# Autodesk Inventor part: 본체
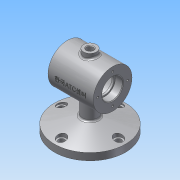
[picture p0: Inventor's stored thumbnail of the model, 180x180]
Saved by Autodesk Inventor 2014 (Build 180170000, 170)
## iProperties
Created: 2018-12
Part Number: 본체
Material: 알루미늄 6061
Document SubType Name: Modeling
Designer: sda
Mass: 688.56 g
Surface Area: 557.83 cm^2
Volume: 254.081 cm^3
Density: 2.71 g/cm^3
Appearance: 알루미늄 - 평지
Author: sda
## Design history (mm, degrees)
sketch "스케치1"
  geometry: C1 r 55 at (0, 0); 1 further point
  constraints: 1 centre point, 1 coincident
  dimensions: "d0" = 110 diameter of C1
extrude "돌출1" new body sketch "스케치1" distance "d1" = 11; taper "d2" = 0 deg
node "작업 평면1"
sketch "스케치2"
  geometry: L1 (55, 11)-(-55, 11) reference; L2 (55, 11)-(0, 25.737); L3 (0, 25.737)-(0, 11); L4 (55, 0)-(55, 11) reference; 1 further point
  constraints: 4 end point, 1 midpoint, 1 vertical
  dimensions: "d5" = 75 deg angle of L4 L2
revolve "회전1" sketch "스케치2" stored, may be unused: angle "d6" = 90 deg
node "작업 평면2"
node "작업 평면3"
node "작업 평면5"
sketch "스케치6"
  geometry: L1 (0, 0)-(35, 0); L2 (0, 0)-(-35, 0); L3 (-35, 0)-(-35, -30); L4 (-35, -30)-(35, -30); L5 (35, -30)-(35, 0); C1 r 55 at (0, 0) reference; 2 further points
  constraints: 10 end point, 2 perpendicular, 1 collinear, 1 horizontal, 1 parallel
  dimensions: "d38" = 35 distance of L1.start L1.end; "d39" = 35 distance of L1.start L2.end; "d40" = 30 distance of L2.end L3.end
revolve "회전4" sketch "스케치6" stored, may be unused: angle "d41" = 90 deg
sketch "스케치7"
  geometry: L1 (0, 25.737)-(55, 11) reference; L2 (55, 11)-(55, 0) reference; L3 (55, 0)-(-55, 0) reference; L4 (-55, 0)-(-55, 11) reference; L5 (-55, 11)-(0, 25.737) reference; L6 (-35, 45)-(-35, 105) reference; L7 (-35, 105)-(35, 105) reference; L8 (35, 105)-(35, 45) reference; L9 (35, 45)-(-35, 45) reference; L10 (55, 11)-(55, 0) reference; L11 (55, 0)-(-55, 0) reference; L12 (-55, 0)-(-55, 11) reference; L13 (-35, 45)-(-35, 105) reference; L14 (-35, 105)-(35, 105) reference; L15 (35, 105)-(35, 45) reference; L16 (35, 45)-(-35, 45) reference; L17 (-35, 75)-(35, 75); L18 (-35, 91)-(-23, 91); L19 (-23, 91)-(-23, 89); L20 (-23, 89)-(-20, 89); L21 (-20, 89)-(-20, 100); L22 (-20, 100)-(20, 100); L23 (20, 100)-(20, 89); L24 (20, 89)-(23, 89); L25 (23, 89)-(23, 91); L26 (23, 91)-(35, 91); L27 (0, 25.737)-(55, 11) reference; L28 (-55, 11)-(0, 25.737) reference; 1 further point
  constraints: 20 end point, 7 parallel, 2 midpoint, 2 perpendicular, 2 point on line
  dimensions: "d42" = 50 diameter of L22 L17; "d44" = 28 diameter of L20 L17; "d45" = 28 diameter of L24 L17; "d46" = 32 diameter of L26 L17; "d47" = 32 diameter of L18 L17; "d48" = 3 distance between parallel lines of L21 L19; "d49" = 3 distance between parallel lines of L25 L23; "d50" = 40 distance between parallel lines of L23 L21; "d51" = 12 distance between parallel lines of L19 L6
revolve "회전5" sketch "스케치7" stored, may be unused: angle "d52" = 90 deg
chamfer "모따기3" distance "d53" = 1; stored, may be unused: second distance "d54" = 2, angle "d55" = 45 deg
chamfer "모따기4" distance "d56" = 1; stored, may be unused: second distance "d57" = 2, angle "d58" = 45 deg
fillet "모깎기3" dims "d59" = 0.3
fillet "모깎기4" dims "d60" = 3
sketch "스케치8"
  geometry: L1 (35, 45)-(35, 105) reference; L2 (-35, 45)-(-35, 105) reference; L3 (-35, 45)-(35, 45) reference; L4 (0, 25.737)-(55, 11) reference; L5 (0, 45)-(0, 25.737); L6 (12, 45)-(12, 22.522); 1 further point
  constraints: 4 end point, 2 point on line, 1 midpoint, 1 parallel, 1 perpendicular
  dimensions: "d61" = 12 distance between parallel lines of L6 L5
revolve "회전6" sketch "스케치8" stored, may be unused: angle "d62" = 90 deg
sketch "스케치9"
  geometry: A1 r 12 centre (0, 0) between (12, 0) and (-12, 0) reference; 1 further point
  constraints: 1 coincident, 1 horizontal alignment, 2 other
extrude "돌출2" join sketch "스케치9" stored distance "d63" = 10; taper "d64" = 0 deg
node "작업 평면6"
sketch "스케치10"
  geometry: C1 r 10 at (0, 0); 1 further point
  constraints: 1 centre point, 1 coincident
  dimensions: "d66" = 20 diameter of C1
extrude "돌출3" join sketch "스케치10" stored distance "d67" = 10; taper "d68" = 0 deg
hole "구멍1" diameter "d71" = 10; stored, may be unused: countersink angle "d75" = 90 deg, drill point angle "d77" = 118 deg; dims "d69" = 10, "d70" = 10, "d72" = 6, "d73" = 4, "d74" = 2, "d76" = 8
chamfer "모따기5" distance "d78" = 1; stored, may be unused: second distance "d79" = 2, angle "d80" = 45 deg
sketch "스케치11" dims "d81" = 46
  geometry: C1 r 17 at (0, 0) reference; 3 further points
  constraints: 2 vertical alignment, 1 coincident, 2 other
hole "구멍2" sketch "스케치11" at (0, 23) diameter "d82" = 3.242; stored, may be unused: countersink angle "d86" = 90 deg, drill point angle "d88" = 118 deg; dims "d83" = 8, "d84" = 4, "d85" = 2, "d87" = 10
sketch "스케치12" dims "d92" = 88
  geometry: C1 r 55 at (0, 0) reference; 2 further points
  constraints: 2 vertical alignment, 1 coincident, 2 other
hole "구멍3" sketch "스케치12" at (0, 44) diameter "d93" = 9; stored, may be unused: countersink angle "d97" = 90 deg, drill point angle "d99" = 118 deg; dims "d94" = 8, "d95" = 4, "d96" = 2, "d98" = 10
node "작업 평면7"
sketch "스케치13"
  geometry: C1 r 4.5 at (0, 44) reference; C2 r 55 at (0, 0) reference; C3 r 7 at (0, 44); 1 further point
  constraints: 1 centre point, 1 coincident
  dimensions: "d101" = 14 diameter of C3
extrude "돌출4" cut sketch "스케치13" distance "d102" = 10; taper "d103" = 0 deg
fillet "모깎기5" dims "d107" = 3
node "작업 평면8"
sketch "스케치14"
  geometry: L1 (-35, -30)-(-35, 30) reference; L2 (35, -30)-(35, 30) reference; L3 (-24.887, 3.602)-(24.887, 3.602); L4 (24.887, 3.602)-(24.887, -3.602); L5 (24.887, -3.602)-(-24.887, -3.602); L6 (-24.887, -3.602)-(-24.887, 3.602); L7 (0, 3.602)-(0, -3.602); L8 (-24.887, 0)-(24.887, 0); L9 (-35, 30)-(35, 30) reference; 2 further points
  constraints: 4 end point, 4 midpoint, 1 vertical alignment, 2 other
  dimensions: "d108" = 30 distance between parallel lines of L8 L9
feature "엠보싱1" sketch "스케치14" dims "d109" = 0.5, "d110" = 0
node "솔리드1"
pattern_circular "원형 패턴1" dims angle "d90" = 360 deg
mirror "대칭1"
pattern_circular "원형 패턴2" dims angle "d105" = 360 deg
node "투영된 루프1"
node "투영된 루프2"
node "절단 모서리 투영2"
node "절단 모서리 투영3"
node "절단 모서리 투영4"
other parameters: "d3" = 0, "d7" = -75, "d11" = 0, "d35" = -75, "d65" = -112
